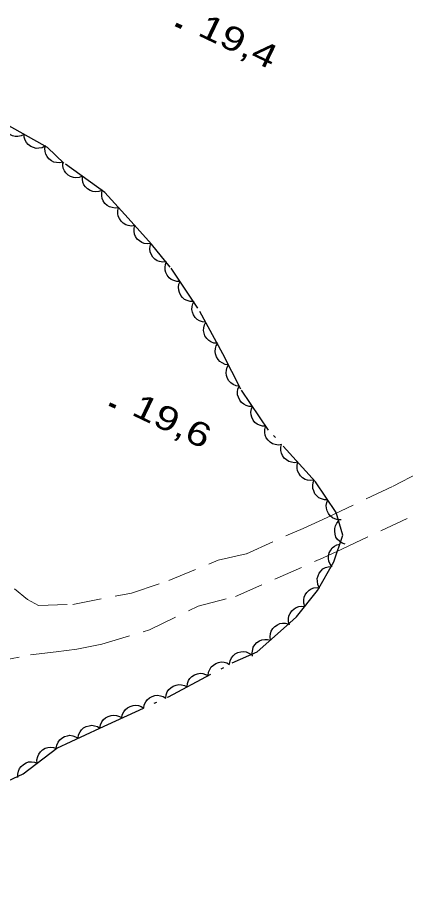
# Model space of a CAD drawing. Extents: x 355726 to 357533, y 5103782 to 5105258.
# Drawn here: x 356467.9 to 356492.1, y 5104778.7 to 5104833.4 of the extents above; entities that cross this region are included whole.
import ezdxf

# ---------------------------------------------------------------- set-up
doc = ezdxf.new("R2010")
doc.units = 0
doc.header["$LTSCALE"] = 0.6
doc.linetypes.add('DOT_DASHED', pattern=[7.7, 5, -1.2, 0.3, -1.2])
doc.linetypes.add('MEDIUM_DASHED', pattern=[4.5, 3, -1.5])
for name, color, linetype, lineweight in [('19', 7, 'Continuous', 13), ('3', 7, 'Continuous', 140), ('44', 7, 'Continuous', 25)]:
    doc.layers.add(name, color=color, linetype=linetype, lineweight=lineweight)

msp = doc.modelspace()

# ---------------------------------------------------------------- linework, layer by layer
at = {"layer": '19', "linetype": 'MEDIUM_DASHED'}
for points in [[(356467.73, 5104797.82), (356468.54, 5104797.16), (356469.22, 5104796.78), (356471.36, 5104796.85), (356475.03, 5104797.56), (356477.34, 5104798.33), (356480.41, 5104799.6), (356482.18, 5104800.01), (356485.71, 5104801.59), (356487.21, 5104802.26), (356491.33, 5104804.22), (356499.64, 5104808.5)], [(356417.66, 5104778.65), (356427.86, 5104783.63), (356433.44, 5104786.63), (356434.42, 5104787.03), (356437.89, 5104787.55), (356441.57, 5104787.95), (356443.55, 5104788.12), (356445.92, 5104788.46), (356447.56, 5104788.73), (356450.59, 5104789.49), (356455.2, 5104790.65), (356456.85, 5104791.11), (356458.73, 5104791.63), (356463.61, 5104792.74), (356468.73, 5104793.7), (356470.32, 5104793.89), (356471.61, 5104794.06), (356473.17, 5104794.37), (356476.15, 5104795.26), (356479.17, 5104796.73), (356481.49, 5104797.34), (356486.97, 5104799.76), (356488.12, 5104800.29), (356492.3, 5104802.26)]]:
    msp.add_lwpolyline(points, dxfattribs=at)
at = {"layer": '3'}
for p, q in [((356477.78, 5104832.99), (356478.14, 5104832.82)), ((356473.66, 5104809.33), (356474.02, 5104809.16))]:
    msp.add_line(p, q, dxfattribs=at)
at = {"layer": '44', "linetype": 'DOT_DASHED'}
msp.add_lwpolyline([(356465.59, 5104785.05), (356468.27, 5104786.3), (356470.36, 5104787.89), (356473.05, 5104789.14), (356477.32, 5104791.09), (356481.29, 5104793.2), (356482.86, 5104793.89), (356484.48, 5104795.35), (356485.29, 5104796.08), (356486.61, 5104797.71), (356487.63, 5104799.51), (356488.18, 5104801.17), (356487.78, 5104802.58), (356486.49, 5104804.49), (356483.56, 5104807.71), (356481.84, 5104810.26), (356480.72, 5104812.47), (356479.16, 5104815.32), (356477.44, 5104817.87), (356476.27, 5104819.31), (356474.81, 5104820.92), (356473.35, 5104822.53), (356470.81, 5104824.35), (356469.78, 5104825.32), (356468.28, 5104826.17), (356466.48, 5104827.18)], dxfattribs=at)
at = {"layer": '44'}
for points in [[(356468.33, 5104826.14), (356468.14, 5104826.05), (356467.94, 5104826.02), (356467.78, 5104826.01), (356467.61, 5104826.05), (356467.44, 5104826.13), (356467.29, 5104826.25), (356467.17, 5104826.36), (356467.09, 5104826.52), (356467.03, 5104826.7), (356467.02, 5104826.88)], [(356469.63, 5104825.4), (356469.45, 5104825.31), (356469.24, 5104825.28), (356469.08, 5104825.27), (356468.91, 5104825.32), (356468.74, 5104825.39), (356468.59, 5104825.51), (356468.48, 5104825.63), (356468.4, 5104825.79), (356468.34, 5104825.96), (356468.33, 5104826.14)], [(356470.75, 5104824.41), (356470.54, 5104824.36), (356470.34, 5104824.38), (356470.18, 5104824.41), (356470.03, 5104824.5), (356469.88, 5104824.61), (356469.77, 5104824.76), (356469.68, 5104824.9), (356469.64, 5104825.07), (356469.63, 5104825.26), (356469.66, 5104825.44)], [(356471.96, 5104823.53), (356471.76, 5104823.45), (356471.56, 5104823.44), (356471.4, 5104823.45), (356471.23, 5104823.52), (356471.07, 5104823.61), (356470.94, 5104823.75), (356470.84, 5104823.87), (356470.77, 5104824.04), (356470.74, 5104824.22), (356470.74, 5104824.4)], [(356473.18, 5104822.65), (356472.98, 5104822.58), (356472.78, 5104822.57), (356472.62, 5104822.58), (356472.45, 5104822.64), (356472.29, 5104822.74), (356472.16, 5104822.87), (356472.06, 5104823), (356471.99, 5104823.16), (356471.96, 5104823.35), (356471.96, 5104823.53)], [(356474.22, 5104821.57), (356474.01, 5104821.54), (356473.81, 5104821.58), (356473.65, 5104821.62), (356473.5, 5104821.72), (356473.37, 5104821.84), (356473.26, 5104822), (356473.19, 5104822.15), (356473.17, 5104822.32), (356473.17, 5104822.51), (356473.21, 5104822.68)], [(356475.22, 5104820.46), (356475.02, 5104820.43), (356474.82, 5104820.46), (356474.66, 5104820.51), (356474.51, 5104820.61), (356474.38, 5104820.73), (356474.27, 5104820.89), (356474.2, 5104821.04), (356474.17, 5104821.21), (356474.17, 5104821.4), (356474.22, 5104821.57)], [(356476.23, 5104819.35), (356476.03, 5104819.32), (356475.82, 5104819.35), (356475.67, 5104819.4), (356475.52, 5104819.5), (356475.38, 5104819.62), (356475.28, 5104819.78), (356475.21, 5104819.93), (356475.18, 5104820.1), (356475.18, 5104820.29), (356475.22, 5104820.46)], [(356477.18, 5104818.19), (356476.97, 5104818.17), (356476.77, 5104818.21), (356476.62, 5104818.27), (356476.48, 5104818.37), (356476.35, 5104818.5), (356476.25, 5104818.67), (356476.19, 5104818.82), (356476.17, 5104819), (356476.18, 5104819.18), (356476.23, 5104819.35)], [(356478.05, 5104816.97), (356477.84, 5104816.97), (356477.65, 5104817.03), (356477.5, 5104817.1), (356477.36, 5104817.21), (356477.25, 5104817.36), (356477.17, 5104817.53), (356477.12, 5104817.68), (356477.11, 5104817.86), (356477.14, 5104818.04), (356477.21, 5104818.21)], [(356478.89, 5104815.72), (356478.68, 5104815.72), (356478.48, 5104815.78), (356478.33, 5104815.85), (356478.2, 5104815.97), (356478.09, 5104816.11), (356478.01, 5104816.29), (356477.96, 5104816.44), (356477.95, 5104816.62), (356477.98, 5104816.8), (356478.05, 5104816.97)], [(356479.65, 5104814.43), (356479.44, 5104814.45), (356479.25, 5104814.53), (356479.11, 5104814.61), (356478.99, 5104814.74), (356478.88, 5104814.89), (356478.82, 5104815.07), (356478.78, 5104815.23), (356478.8, 5104815.41), (356478.84, 5104815.59), (356478.93, 5104815.75)], [(356480.37, 5104813.12), (356480.16, 5104813.14), (356479.97, 5104813.21), (356479.83, 5104813.29), (356479.71, 5104813.42), (356479.6, 5104813.58), (356479.54, 5104813.76), (356479.5, 5104813.92), (356479.52, 5104814.09), (356479.56, 5104814.27), (356479.65, 5104814.43)], [(356481.07, 5104811.79), (356480.86, 5104811.81), (356480.67, 5104811.9), (356480.53, 5104811.98), (356480.42, 5104812.12), (356480.32, 5104812.27), (356480.26, 5104812.46), (356480.23, 5104812.62), (356480.25, 5104812.79), (356480.3, 5104812.97), (356480.39, 5104813.13)], [(356481.74, 5104810.45), (356481.54, 5104810.48), (356481.35, 5104810.56), (356481.21, 5104810.65), (356481.09, 5104810.78), (356481, 5104810.93), (356480.94, 5104811.12), (356480.91, 5104811.28), (356480.93, 5104811.45), (356480.98, 5104811.63), (356481.07, 5104811.79)], [(356482.56, 5104809.19), (356482.35, 5104809.19), (356482.16, 5104809.25), (356482.01, 5104809.32), (356481.87, 5104809.44), (356481.76, 5104809.58), (356481.68, 5104809.76), (356481.63, 5104809.91), (356481.63, 5104810.09), (356481.65, 5104810.27), (356481.72, 5104810.44)], [(356483.4, 5104807.95), (356483.19, 5104807.95), (356482.99, 5104808.01), (356482.84, 5104808.08), (356482.71, 5104808.19), (356482.6, 5104808.34), (356482.52, 5104808.51), (356482.47, 5104808.67), (356482.46, 5104808.84), (356482.49, 5104809.03), (356482.56, 5104809.19)], [(356484.37, 5104806.81), (356484.17, 5104806.78), (356483.97, 5104806.82), (356483.81, 5104806.86), (356483.66, 5104806.96), (356483.53, 5104807.08), (356483.42, 5104807.24), (356483.35, 5104807.39), (356483.32, 5104807.56), (356483.32, 5104807.75), (356483.37, 5104807.92)], [(356485.38, 5104805.71), (356485.18, 5104805.68), (356484.98, 5104805.71), (356484.82, 5104805.75), (356484.67, 5104805.85), (356484.53, 5104805.97), (356484.43, 5104806.13), (356484.36, 5104806.28), (356484.33, 5104806.45), (356484.33, 5104806.64), (356484.37, 5104806.81)], [(356486.39, 5104804.6), (356486.19, 5104804.57), (356485.99, 5104804.6), (356485.83, 5104804.64), (356485.68, 5104804.74), (356485.54, 5104804.86), (356485.44, 5104805.03), (356485.37, 5104805.17), (356485.34, 5104805.34), (356485.34, 5104805.53), (356485.38, 5104805.71)], [(356487.25, 5104803.37), (356487.04, 5104803.37), (356486.85, 5104803.43), (356486.7, 5104803.49), (356486.56, 5104803.61), (356486.45, 5104803.75), (356486.37, 5104803.93), (356486.32, 5104804.08), (356486.31, 5104804.26), (356486.34, 5104804.44), (356486.41, 5104804.61)], [(356488.09, 5104802.12), (356487.88, 5104802.12), (356487.69, 5104802.18), (356487.54, 5104802.25), (356487.4, 5104802.37), (356487.29, 5104802.51), (356487.21, 5104802.68), (356487.16, 5104802.84), (356487.15, 5104803.02), (356487.18, 5104803.2), (356487.25, 5104803.37)], [(356488.34, 5104800.61), (356488.14, 5104800.67), (356487.98, 5104800.79), (356487.85, 5104800.9), (356487.76, 5104801.05), (356487.7, 5104801.22), (356487.68, 5104801.41), (356487.68, 5104801.58), (356487.73, 5104801.75), (356487.81, 5104801.91), (356487.93, 5104802.05)], [(356487.52, 5104799.19), (356487.4, 5104799.35), (356487.32, 5104799.55), (356487.29, 5104799.71), (356487.3, 5104799.88), (356487.34, 5104800.06), (356487.43, 5104800.23), (356487.52, 5104800.37), (356487.66, 5104800.47), (356487.82, 5104800.56), (356488, 5104800.61)], [(356486.72, 5104797.91), (356486.63, 5104798.1), (356486.6, 5104798.3), (356486.59, 5104798.46), (356486.64, 5104798.63), (356486.71, 5104798.8), (356486.83, 5104798.95), (356486.95, 5104799.07), (356487.11, 5104799.15), (356487.28, 5104799.2), (356487.46, 5104799.22)], [(356485.81, 5104796.72), (356485.75, 5104796.92), (356485.75, 5104797.13), (356485.77, 5104797.29), (356485.84, 5104797.45), (356485.95, 5104797.6), (356486.09, 5104797.73), (356486.22, 5104797.83), (356486.39, 5104797.88), (356486.58, 5104797.91), (356486.76, 5104797.89)], [(356484.87, 5104795.56), (356484.81, 5104795.76), (356484.81, 5104795.96), (356484.83, 5104796.13), (356484.9, 5104796.29), (356485, 5104796.44), (356485.15, 5104796.57), (356485.28, 5104796.66), (356485.45, 5104796.71), (356485.63, 5104796.74), (356485.81, 5104796.72)], [(356483.68, 5104794.63), (356483.65, 5104794.83), (356483.68, 5104795.03), (356483.73, 5104795.19), (356483.82, 5104795.34), (356483.95, 5104795.47), (356484.11, 5104795.58), (356484.26, 5104795.65), (356484.43, 5104795.68), (356484.62, 5104795.67), (356484.79, 5104795.63)], [(356482.56, 5104793.62), (356482.53, 5104793.83), (356482.57, 5104794.03), (356482.61, 5104794.19), (356482.71, 5104794.34), (356482.83, 5104794.47), (356483, 5104794.57), (356483.14, 5104794.65), (356483.32, 5104794.67), (356483.5, 5104794.67), (356483.68, 5104794.63)], [(356481.12, 5104793.13), (356481.16, 5104793.33), (356481.25, 5104793.51), (356481.35, 5104793.65), (356481.48, 5104793.76), (356481.65, 5104793.85), (356481.83, 5104793.89), (356481.99, 5104793.92), (356482.17, 5104793.89), (356482.34, 5104793.82), (356482.49, 5104793.73)], [(356479.8, 5104792.41), (356479.82, 5104792.62), (356479.9, 5104792.8), (356479.99, 5104792.95), (356480.12, 5104793.07), (356480.27, 5104793.17), (356480.45, 5104793.23), (356480.61, 5104793.26), (356480.79, 5104793.24), (356480.97, 5104793.2), (356481.13, 5104793.11)], [(356478.48, 5104791.71), (356478.5, 5104791.91), (356478.58, 5104792.1), (356478.66, 5104792.24), (356478.79, 5104792.36), (356478.95, 5104792.46), (356479.13, 5104792.52), (356479.29, 5104792.56), (356479.46, 5104792.54), (356479.64, 5104792.49), (356479.8, 5104792.41)], [(356477.15, 5104791), (356477.18, 5104791.21), (356477.25, 5104791.4), (356477.34, 5104791.54), (356477.47, 5104791.66), (356477.62, 5104791.76), (356477.8, 5104791.82), (356477.96, 5104791.85), (356478.14, 5104791.84), (356478.32, 5104791.79), (356478.48, 5104791.71)], [(356475.78, 5104790.39), (356475.82, 5104790.59), (356475.91, 5104790.78), (356476, 5104790.91), (356476.14, 5104791.02), (356476.3, 5104791.12), (356476.48, 5104791.17), (356476.64, 5104791.19), (356476.82, 5104791.16), (356476.99, 5104791.1), (356477.15, 5104791.01)], [(356474.42, 5104789.77), (356474.45, 5104789.97), (356474.54, 5104790.15), (356474.64, 5104790.29), (356474.77, 5104790.4), (356474.93, 5104790.49), (356475.12, 5104790.54), (356475.28, 5104790.57), (356475.45, 5104790.54), (356475.63, 5104790.48), (356475.78, 5104790.39)], [(356473.05, 5104789.14), (356473.09, 5104789.35), (356473.18, 5104789.53), (356473.27, 5104789.67), (356473.41, 5104789.78), (356473.57, 5104789.87), (356473.75, 5104789.92), (356473.92, 5104789.94), (356474.09, 5104789.92), (356474.27, 5104789.86), (356474.42, 5104789.77)], [(356471.69, 5104788.51), (356471.73, 5104788.72), (356471.82, 5104788.9), (356471.91, 5104789.04), (356472.04, 5104789.15), (356472.2, 5104789.24), (356472.39, 5104789.29), (356472.55, 5104789.32), (356472.72, 5104789.29), (356472.9, 5104789.23), (356473.05, 5104789.14)], [(356470.33, 5104787.88), (356470.37, 5104788.08), (356470.46, 5104788.27), (356470.55, 5104788.4), (356470.68, 5104788.52), (356470.84, 5104788.61), (356471.03, 5104788.66), (356471.19, 5104788.69), (356471.36, 5104788.66), (356471.54, 5104788.6), (356471.69, 5104788.51)], [(356469.14, 5104786.96), (356469.13, 5104787.17), (356469.18, 5104787.37), (356469.24, 5104787.52), (356469.35, 5104787.66), (356469.48, 5104787.79), (356469.65, 5104787.88), (356469.81, 5104787.94), (356469.98, 5104787.95), (356470.17, 5104787.93), (356470.34, 5104787.87)], [(356467.95, 5104786.06), (356467.94, 5104786.26), (356467.99, 5104786.46), (356468.05, 5104786.62), (356468.15, 5104786.75), (356468.29, 5104786.88), (356468.46, 5104786.97), (356468.61, 5104787.03), (356468.79, 5104787.04), (356468.97, 5104787.02), (356469.14, 5104786.96)]]:
    msp.add_lwpolyline(points, dxfattribs=at)

# ---------------------------------------------------------------- texts
at = {"layer": '3', "width": 1.3}
for s, p in [('19,4   ', (356479.07, 5104832.36)), ('19,6   ', (356474.95, 5104808.7))]:
    msp.add_text(s, height=1.5, rotation=334.423, dxfattribs=at).set_placement(p)

doc.saveas('drawing.dxf')
